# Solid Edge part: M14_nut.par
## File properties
Title: Ecrou hexagonal NF EN 1661 - M14 - 8
Author: TraceParts S.A.
Template: Iso Metric Part.par
Last saved by: Nimesh.N
Revision: 18
Application: TraceParts
Company: TraceParts S.A.
Density: 7833.000 kg/m^3
Accuracy: 0.990
REFERENCE: NF EN 1661 - d M14 - 8
STANDARD: NF EN 1661
NOTE: Classe: 8
DESIGN: Ecrou hexagonal NF EN 1661 - M14 - 8
MATERIAL: Acier
TraceParts.PartNumber: 10-13082008-066825
TraceParts.PartLanguage: fr
TraceParts.InstanceId: 10-13082008-0668253X2V5U9TVXVZ1KXBN7PDJ027I
TraceParts.PartStandardAcronym: NF
TraceParts.PartTitle: Ecrous hexagonaux à embase cylindro-tronconique
TRACEPARTS: TRACEPARTS
TraceParts.PartVersion: 1.2.4
Username: Nimesh.N
Material: Steel
Face Style: Steel
Fill Style: ANSI32(Steel)
Virtual Style: Machined steel
Grouping: Metals\Steel
LibraryName: Materials
Coef. of Thermal Exp: 1.3e-05
Thermal Conductivity: 32.0
Specific Heat: 481.0
Modulus of Elasticity: 199947953000.0
Poisson's Ratio: 0.29
Yield Stress: 262000766.0
Ultimate Stress: 358527364.0
Elongation: 0.0
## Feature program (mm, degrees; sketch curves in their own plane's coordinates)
body "unnamed Body 1"
sketch for "unnamed Cutout 1" plane through (0, 0, 14) normal (0, 0, 1) x-axis (1, 0, 0)
  circle centre (0, 0) radius 7
extrude "unnamed Cutout 1" cut through along -normal
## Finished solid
Body 1: solid body, 17 faces, 34 edges, 20 vertices.
  Faces by surface: plane 8, cone 7, cylinder 1, torus 1
  Edges by curve: spline 18, circle 10, line 6
Bounding box of the edges (mm; curved faces can reach further): 28.750 x 28.750 x 14.000, from (-14.375, -14.375, 0) to (14.375, 14.375, 14).
Cylindrical faces by radius (mm): R7 x1
Conical faces (half-angle, radius in mm at the cone's reference point): 60 deg R7.1875 x1, 60 deg R11.3137 x6
Toroidal faces (ring radius, tube radius in mm): R13.8 r1.15 x1
Planar faces by outward normal: +x 1, +z 1, -x 1, -z 1, oblique 4
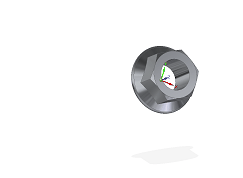
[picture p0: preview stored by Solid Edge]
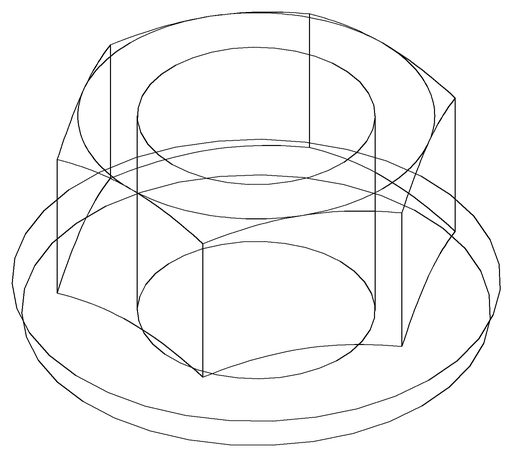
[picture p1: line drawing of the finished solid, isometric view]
